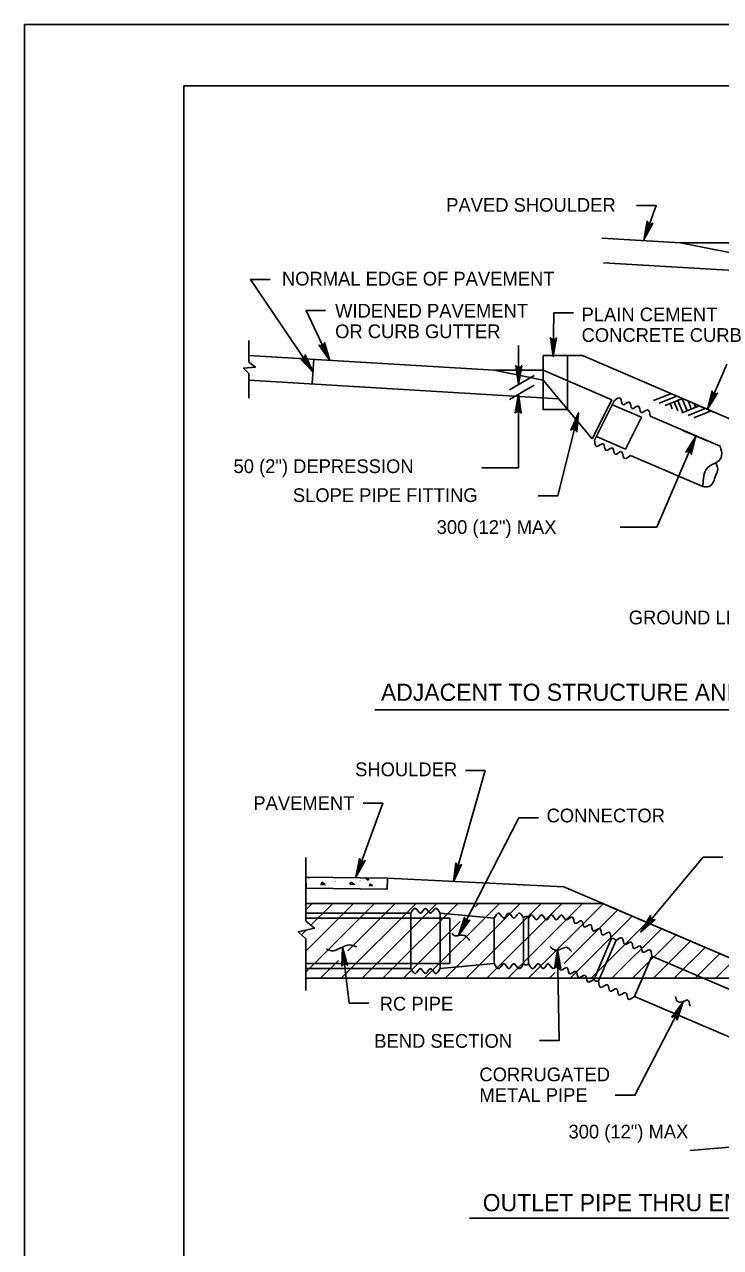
# Model space of a CAD drawing. Extents: x 637898 to 638802, y 298167 to 298761.
# Drawn here: x 637898 to 638068.2, y 298461.7 to 298760.9 of the extents above; entities that cross this region are included whole.
import ezdxf

# ---------------------------------------------------------------- set-up
doc = ezdxf.new("R2010")
doc.units = 0
for name, color, linetype in [('1', 7, 'Continuous'), ('2', 7, 'Continuous'), ('3', 7, 'Continuous'), ('PLT-BNDY', 7, 'Continuous')]:
    doc.layers.add(name, color=color, linetype=linetype)

msp = doc.modelspace()

# ---------------------------------------------------------------- linework, layer by layer
at = {"layer": '1'}
msp.add_lwpolyline([(638722.97, 298181.88), (638722.97, 298745.88), (637936.97, 298745.88), (637936.97, 298181.88), (638722.97, 298181.88), (638722.97, 298208.24), (638522.97, 298208.24), (638522.97, 298272.92), (638722.97, 298272.92), (638722.97, 298301.88), (638522.97, 298301.88), (638522.97, 298181.88), (638601.78, 298181.88), (638601.78, 298208.24), (638601.78, 298181.88), (638678.78, 298181.88), (638678.78, 298208.24), (638678.78, 298195.92), (638722.97, 298195.92)], dxfattribs=at)
at = {"layer": '2'}
for p, q in [((638039.16, 298708.64), (638058.42, 298707.48)), ((638058.42, 298707.48), (638070.42, 298705.08)), ((638039.61, 298702.6), (638074.22, 298700.52)), ((637952.82, 298683.56), (637952.82, 298678.27)), ((637952.82, 298679.88), (638012.82, 298676.28)), ((638018.81, 298672.82), (638018.81, 298682.31)), ((638024.82, 298676.28), (638024.82, 298679.88)), ((638024.82, 298679.88), (638034.42, 298679.88)), ((637968.73, 298679.04), (637968.37, 298673.05)), ((638069.71, 298677.75), (638065, 298666.74)), ((637952.82, 298675.54), (637952.82, 298669.44)), ((637952.82, 298673.87), (638028.62, 298669.32)), ((638012.82, 298676.28), (638024.82, 298673.88)), ((638022.66, 298675.04), (638016.58, 298671.53)), ((638041.62, 298669.08), (638024.82, 298676.28)), ((638024.82, 298673.88), (638036.82, 298659.48)), ((638022.66, 298672.64), (638016.58, 298669.13)), ((638036.82, 298659.48), (638041.62, 298669.08)), ((638037.35, 298659.21), (638042.16, 298668.81)), ((638042.16, 298668.81), (638042.16, 298668.81)), ((638051.85, 298668.88), (638056.07, 298670.56)), ((638053.23, 298668.28), (638057.48, 298669.98)), ((638054.66, 298667.67), (638058.91, 298669.37)), ((638055.87, 298668.15), (638056.38, 298666.88)), ((638056.89, 298668.56), (638057.78, 298666.34)), ((638057.8, 298668.92), (638058.96, 298666)), ((638058.84, 298669.4), (638060.04, 298666.4)), ((638060.27, 298668.78), (638061.05, 298666.83)), ((638061.72, 298668.16), (638062.09, 298667.23)), ((638061.79, 298668.12), (638067.76, 298665.56)), ((638044.36, 298667.87), (638044.36, 298667.87)), ((638044.36, 298667.87), (638044.36, 298667.87)), ((638046.57, 298666.92), (638046.57, 298666.92)), ((638046.57, 298666.92), (638046.57, 298666.92)), ((638048.77, 298665.98), (638048.77, 298665.98)), ((638050.98, 298665.03), (638050.98, 298665.03)), ((638068.11, 298657.69), (638050.98, 298665.03)), ((638058.78, 298665.91), (638063.04, 298667.61)), ((638060.29, 298665.26), (638064.48, 298666.94)), ((638061.71, 298664.65), (638065.91, 298666.33)), ((638053.19, 298664.09), (638053.19, 298664.09)), ((638055.39, 298663.14), (638055.39, 298663.14)), ((638057.6, 298662.2), (638057.6, 298662.2)), ((638037.35, 298659.21), (638037.35, 298659.21)), ((638058.99, 298661.59), (638064.95, 298659.03)), ((638059.8, 298661.25), (638059.8, 298661.25)), ((638062.01, 298660.31), (638062.01, 298660.31)), ((638064.21, 298659.36), (638064.21, 298659.36)), ((638043.97, 298656.38), (638043.97, 298656.38)), ((638066.42, 298658.42), (638066.42, 298658.42)), ((638046.18, 298655.43), (638046.18, 298655.43)), ((638063.89, 298647.84), (638046.18, 298655.43)), ((638048.39, 298654.49), (638048.39, 298654.49)), ((638050.59, 298653.54), (638050.59, 298653.54)), ((638052.8, 298652.6), (638052.8, 298652.6)), ((638055, 298651.65), (638055, 298651.65)), ((638057.21, 298650.71), (638057.21, 298650.71)), ((638059.42, 298649.76), (638059.42, 298649.76)), ((638061.62, 298648.82), (638061.62, 298648.82)), ((638063.83, 298647.87), (638063.83, 298647.87)), ((637966.76, 298557.09), (637966.76, 298541.57)), ((637986.74, 298552.08), (638029.92, 298549.91)), ((638080.36, 298528.3), (638029.92, 298549.91)), ((638039.35, 298545.87), (637966.76, 298545.87)), ((637992.44, 298543.47), (637966.76, 298543.47)), ((638002.04, 298542.27), (637966.76, 298542.27)), ((637984.04, 298542.27), (637984.04, 298542.27)), ((637986.44, 298542.27), (637986.44, 298542.27)), ((637986.44, 298542.27), (637986.44, 298542.27)), ((637988.84, 298542.27), (637988.84, 298542.27)), ((637991.24, 298542.27), (637991.24, 298542.27)), ((637992.44, 298543.47), (637992.44, 298529.95)), ((637993.64, 298542.27), (637993.64, 298542.27)), ((637996.04, 298542.27), (637996.04, 298542.27)), ((637998.44, 298542.27), (637998.44, 298542.27)), ((637999.64, 298543.47), (637999.64, 298529.95)), ((638012.84, 298542.27), (637999.64, 298543.47)), ((638000.84, 298542.27), (638000.84, 298542.27)), ((638002.04, 298542.27), (638002.04, 298531.15)), ((638003.24, 298542.27), (638003.24, 298542.27)), ((638005.64, 298542.27), (638005.64, 298542.27)), ((638008.04, 298542.27), (638008.04, 298542.27)), ((638010.44, 298542.27), (638010.44, 298542.27)), ((638012.84, 298542.27), (638012.84, 298542.27)), ((638012.84, 298531.15), (638012.84, 298542.27)), ((638015.24, 298542.27), (638015.24, 298542.27)), ((638017.64, 298542.27), (638017.64, 298542.27)), ((638020.04, 298531.15), (638020.04, 298542.27)), ((638020.04, 298542.27), (638020.04, 298542.27)), ((638021.24, 298531.15), (638021.24, 298542.27)), ((638020.84, 298541.87), (638020.84, 298541.87)), ((638023.24, 298541.87), (638023.24, 298541.87)), ((638025.64, 298541.87), (638025.64, 298541.87)), ((638028.04, 298541.87), (638028.04, 298541.87)), ((638030.44, 298541.87), (638030.44, 298541.87)), ((638032.66, 298541), (638032.66, 298541)), ((638034.87, 298540.06), (638034.87, 298540.06)), ((637966.76, 298537.23), (637966.76, 298524.61)), ((638037.08, 298539.11), (638037.08, 298539.11)), ((638041.49, 298537.22), (638037.27, 298527.37)), ((638042.59, 298536.75), (638038.37, 298526.9)), ((638039.28, 298538.17), (638039.28, 298538.17)), ((638041.49, 298537.22), (638041.49, 298537.22)), ((638002.04, 298531.15), (637966.76, 298531.15)), ((637984.04, 298531.15), (637984.04, 298531.15)), ((637986.44, 298531.15), (637986.44, 298531.15)), ((637986.44, 298531.15), (637986.44, 298531.15)), ((637988.84, 298531.15), (637988.84, 298531.15)), ((637991.24, 298531.15), (637991.24, 298531.15)), ((637993.64, 298531.15), (637993.64, 298531.15)), ((637996.04, 298531.15), (637996.04, 298531.15)), ((637998.44, 298531.15), (637998.44, 298531.15)), ((638012.84, 298531.15), (637999.64, 298529.95)), ((638000.84, 298531.15), (638000.84, 298531.15)), ((638003.24, 298531.15), (638003.24, 298531.15)), ((638005.64, 298531.15), (638005.64, 298531.15)), ((638008.04, 298531.15), (638008.04, 298531.15)), ((638010.44, 298531.15), (638010.44, 298531.15)), ((638012.84, 298531.15), (638012.84, 298531.15)), ((638015.24, 298531.15), (638015.24, 298531.15)), ((638017.64, 298531.15), (638017.64, 298531.15)), ((638020.04, 298531.15), (638020.04, 298531.15)), ((638021.24, 298531.15), (638021.24, 298531.15)), ((638023.64, 298531.15), (638023.64, 298531.15)), ((638026.04, 298531.15), (638026.04, 298531.15)), ((638028.44, 298531.15), (638028.44, 298531.15)), ((638051.41, 298532.97), (638047.19, 298523.12)), ((638051.41, 298532.97), (638077.37, 298521.84)), ((637992.44, 298529.95), (637966.76, 298529.95)), ((638081.26, 298527.55), (637966.76, 298527.55)), ((638030.65, 298530.21), (638030.65, 298530.21)), ((638032.86, 298529.26), (638032.86, 298529.26)), ((638035.06, 298528.32), (638035.06, 298528.32)), ((638037.27, 298527.37), (638037.27, 298527.37)), ((638047.19, 298523.12), (638073.15, 298512)), ((638006.78, 298468.88), (638148.19, 298468.88))]:
    msp.add_line(p, q, dxfattribs=at)
for points in [[(638047.62, 298716.61), (638052.43, 298716.61), (638049.47, 298708.19)], [(638051.43, 298712.12), (638051.08, 298712.07), (638049.47, 298708.19), (638051.43, 298712.12), (638051.69, 298712.27), (638049.47, 298708.19), (638050.67, 298712.22), (638050.42, 298712.46), (638049.47, 298708.19), (638050.3, 298712.76), (638050.42, 298712.46)], [(638058.42, 298707.48), (638075.21, 298707.48)], [(637958.05, 298698.47), (637953.25, 298698.47), (637968.54, 298675.82)], [(637971.63, 298690.94), (637966.83, 298690.94), (637972.66, 298678.61)], [(638032.22, 298690.32), (638027.42, 298690.32), (638027.29, 298679.64)], [(637971.29, 298682.79), (637971.07, 298682.51), (637972.66, 298678.61), (637971.29, 298682.79), (637971.36, 298683.07), (637972.66, 298678.61), (637970.68, 298682.32), (637970.33, 298682.32), (637972.66, 298678.61), (637970.04, 298682.44), (637970.33, 298682.32)], [(638027.89, 298683.99), (638027.57, 298683.83), (638027.29, 298679.64), (638027.89, 298683.99), (638028.08, 298684.21), (638027.29, 298679.64), (638027.14, 298683.84), (638026.83, 298683.99), (638027.29, 298679.64), (638026.62, 298684.23), (638026.83, 298683.99)], [(637966.56, 298679.74), (637966.38, 298679.42), (637968.54, 298675.82), (637966.56, 298679.74), (637966.59, 298680.03), (637968.54, 298675.82), (637966.02, 298679.18), (637965.68, 298679.13), (637968.54, 298675.82), (637965.37, 298679.21), (637965.68, 298679.13)], [(638012.82, 298676.28), (638024.82, 298676.28), (638024.82, 298666.68), (638030.82, 298666.68), (638030.82, 298679.88)], [(638034.41, 298679.87), (638071.24, 298664.08)], [(637952.82, 298678.27), (637954.45, 298677.05), (637951.55, 298676.81), (637952.82, 298675.54)], [(638019.41, 298677.17), (638019.09, 298677.01), (638018.81, 298672.82), (638019.41, 298677.17), (638019.6, 298677.39), (638018.81, 298672.82), (638018.65, 298677.01), (638018.34, 298677.17), (638018.81, 298672.82), (638018.13, 298677.41), (638018.34, 298677.17)], [(638067.22, 298670.53), (638066.87, 298670.51), (638065, 298666.74), (638067.22, 298670.53), (638067.48, 298670.66), (638065, 298666.74), (638066.46, 298670.68), (638066.24, 298670.94), (638065, 298666.74), (638066.14, 298671.24), (638066.24, 298670.94)], [(638018.2, 298666.06), (638018.52, 298666.22), (638018.81, 298670.42), (638018.2, 298666.06), (638018.01, 298665.84), (638018.81, 298670.42), (638018.96, 298666.22), (638019.27, 298666.06), (638018.81, 298670.42), (638019.48, 298665.82), (638019.27, 298666.06)], [(638018.81, 298670.42), (638018.81, 298652.42)], [(638023.59, 298645.54), (638028.4, 298645.54), (638033.45, 298665.88)], [(638031.87, 298661.78), (638032.21, 298661.86), (638033.45, 298665.88), (638031.87, 298661.78), (638031.63, 298661.61), (638033.45, 298665.88), (638032.64, 298661.76), (638032.91, 298661.54), (638033.45, 298665.88), (638033.05, 298661.26), (638032.91, 298661.54)], [(638037.84, 298660.09), (638044.98, 298657.03), (638048.87, 298664.8), (638041.72, 298667.87)], [(638062.2, 298660.21), (638052.65, 298637.94)], [(638059.97, 298656.42), (638060.33, 298656.45), (638062.2, 298660.21), (638059.97, 298656.42), (638059.71, 298656.29), (638062.2, 298660.21), (638060.73, 298656.28), (638060.96, 298656.01), (638062.2, 298660.21), (638061.06, 298655.71), (638060.96, 298656.01)], [(638009.81, 298652.42), (638018.81, 298652.42)], [(638052.65, 298637.94), (638043.65, 298637.94)], [(638005.84, 298578.42), (638010.64, 298578.42), (638002.94, 298551.18)], [(637980.83, 298570.38), (637985.63, 298570.38), (637979.05, 298552.3)], [(638023.7, 298566.81), (638018.9, 298566.81), (638004.11, 298538.03)], [(638068.8, 298557.21), (638064, 298557.21), (638048.7, 298538.9)], [(637981.05, 298556.2), (637980.7, 298556.16), (637979.05, 298552.3), (637981.05, 298556.2), (637981.31, 298556.35), (637979.05, 298552.3), (637980.29, 298556.31), (637980.05, 298556.56), (637979.05, 298552.3), (637979.93, 298556.85), (637980.05, 298556.56)], [(638004.65, 298555.22), (638004.3, 298555.15), (638002.94, 298551.18), (638004.65, 298555.22), (638004.89, 298555.39), (638002.94, 298551.18), (638003.88, 298555.27), (638003.62, 298555.5), (638002.94, 298551.18), (638003.48, 298555.79), (638003.62, 298555.5)], [(637966.84, 298549.64), (637986.71, 298549.39), (637986.74, 298552.08), (637966.77, 298552.32)], [(637967.52, 298552.05), (637967.24, 298552.32)], [(637967.52, 298552.31), (637967.52, 298552.05)], [(637981.38, 298552.14), (637982.01, 298551.58)], [(637982.01, 298551.58), (637982.22, 298552.13)], [(637983.98, 298552.05), (637983.91, 298552.11)], [(637983.98, 298552.11), (637983.98, 298552.05)], [(637966.76, 298529.07), (637983.57, 298545.87)], [(637966.76, 298534.16), (637978.48, 298545.87)], [(637966.76, 298544.34), (637968.3, 298545.87)], [(637968.03, 298540.52), (637973.39, 298545.87)], [(637975.43, 298527.55), (637993.75, 298545.87)], [(637977.05, 298534.26), (637988.66, 298545.87)], [(637980.53, 298527.55), (637998.84, 298545.87)], [(637985.62, 298527.55), (638003.93, 298545.87)], [(637995.8, 298527.55), (638014.12, 298545.87)], [(638000.89, 298527.55), (638019.21, 298545.87)], [(638005.98, 298527.55), (638024.3, 298545.87)], [(638008.09, 298544.94), (638009.02, 298545.87)], [(638011.07, 298527.55), (638029.39, 298545.87)], [(638016.16, 298527.55), (638034.48, 298545.87)], [(638021.26, 298527.55), (638039.5, 298545.8)], [(638006.59, 298541.66), (638006.24, 298541.66), (638004.11, 298538.03), (638006.59, 298541.66), (638006.86, 298541.77), (638004.11, 298538.03), (638005.84, 298541.85), (638005.64, 298542.13), (638004.11, 298538.03), (638005.56, 298542.44), (638005.64, 298542.13)], [(638029.96, 298531.16), (638043.07, 298544.28)], [(638031.44, 298527.55), (638046.63, 298542.75)], [(638051.92, 298541.89), (638051.57, 298541.97), (638048.7, 298538.9), (638051.92, 298541.89), (638052.21, 298541.94), (638048.7, 298538.9), (638051.23, 298542.25), (638051.09, 298542.57), (638048.7, 298538.9), (638051.08, 298542.88), (638051.09, 298542.57)], [(637966.76, 298541.57), (637968.89, 298539.81), (637964.95, 298538.94), (637966.76, 298537.23)], [(637965.73, 298538.21), (637966.88, 298539.36)], [(637990.71, 298527.55), (638004.57, 298541.42)], [(638036.53, 298527.55), (638050.2, 298541.22)], [(638041.62, 298527.55), (638053.76, 298539.69)], [(638046.71, 298527.55), (638057.32, 298538.17)], [(638051.8, 298527.55), (638060.89, 298536.64)], [(637975.72, 298530.8), (637976.01, 298531), (637975.75, 298535.2), (637975.72, 298530.8), (637975.56, 298530.56), (637975.75, 298535.2), (637976.45, 298531.06), (637976.78, 298530.94), (637975.75, 298535.2), (637977.01, 298530.73), (637976.78, 298530.94)], [(637982.17, 298521.49), (637977.37, 298521.49), (637975.75, 298535.2)], [(638023.92, 298512.33), (638028.72, 298512.33), (638028.3, 298534.57)], [(638027.83, 298530.2), (638028.14, 298530.37), (638028.3, 298534.57), (638027.83, 298530.2), (638027.64, 298529.97), (638028.3, 298534.57), (638028.58, 298530.38), (638028.9, 298530.23), (638028.3, 298534.57), (638029.11, 298530), (638028.9, 298530.23)], [(638056.89, 298527.55), (638064.45, 298535.11)], [(638061.98, 298527.55), (638068.02, 298533.59)], [(637970.34, 298527.55), (637974.74, 298531.95)], [(638067.08, 298527.55), (638071.58, 298532.06)], [(638026.35, 298527.55), (638027.74, 298528.95)], [(638042.45, 298498.94), (638047.25, 298498.94), (638059.06, 298521.77)], [(638056.57, 298518.15), (638056.92, 298518.15), (638059.06, 298521.77), (638056.57, 298518.15), (638056.3, 298518.04), (638059.06, 298521.77), (638057.31, 298517.95), (638057.52, 298517.67), (638059.06, 298521.77), (638057.6, 298517.36), (638057.52, 298517.67)], [(638060.82, 298485.41), (638070.42, 298486.24)]]:
    msp.add_lwpolyline(points, dxfattribs=at)
for points in [[(637966.77, 298552.32), (637986.74, 298552.08), (637986.71, 298549.39), (637966.84, 298549.64)], [(637970.43, 298550.43), (637970.8, 298551.04), (637971.44, 298550.48)], [(637977.52, 298550.59), (637977.8, 298551.04), (637978.7, 298550.54)], [(637982.33, 298550.14), (637982.56, 298550.59), (637983.09, 298550.26)], [(637968.89, 298539.81), (637966.76, 298541.57), (637966.76, 298545.87), (638039.35, 298545.87), (638080.36, 298528.3), (638081.26, 298527.55), (637966.76, 298527.55), (637966.76, 298537.23), (637964.95, 298538.94)]]:
    msp.add_lwpolyline(points, close=True, dxfattribs=at)
for centre, radius, start, end in [((638020.64, 298542.07), 0.633, 18.7071, 161.2929), ((638020.64, 298531.51), 0.698, 210.7717, 329.2283)]:
    msp.add_arc(centre, radius, start, end, dxfattribs=at)
for points in [[(638050.98, 298665.03), (638050.35, 298666.61), (638048.77, 298665.98), (638048.14, 298667.55), (638046.57, 298666.92), (638045.94, 298668.5), (638044.36, 298667.87), (638043.73, 298669.45), (638042.16, 298668.81)], [(638037.35, 298659.21), (638037.98, 298657.64), (638039.56, 298658.27), (638040.19, 298656.69), (638041.77, 298657.32), (638042.4, 298655.75), (638043.97, 298656.38), (638044.6, 298654.8), (638046.18, 298655.43)], [(638068.11, 298657.69), (638068.46, 298655.35), (638067.53, 298653.94), (638065.49, 298652.85), (638064.24, 298650.97), (638063.93, 298648.63), (638063.89, 298647.84)], [(638063.89, 298647.84), (638065.34, 298647.85), (638066.43, 298648.94), (638067.06, 298650.66), (638067.53, 298652.07), (638067.06, 298653.63)], [(637999.64, 298543.47), (637998.44, 298544.67), (637997.24, 298543.47), (637996.04, 298544.67), (637994.84, 298543.47), (637993.64, 298544.67), (637992.44, 298543.47)], [(638020.04, 298542.27), (638018.84, 298543.47), (638017.64, 298542.27), (638016.44, 298543.47), (638015.24, 298542.27), (638014.04, 298543.47), (638012.84, 298542.27)], [(638041.49, 298537.22), (638040.86, 298538.8), (638039.28, 298538.17), (638038.65, 298539.74), (638037.08, 298539.11), (638036.45, 298540.69), (638034.87, 298540.06), (638034.24, 298541.63), (638032.66, 298541), (638031.99, 298542.55), (638030.44, 298541.87), (638029.24, 298543.07), (638028.04, 298541.87), (638026.84, 298543.07), (638025.64, 298541.87), (638024.44, 298543.07), (638023.24, 298541.87), (638022.04, 298543.07), (638021.26, 298542.29)], [(638002.57, 298538.61), (638003.05, 298538.03), (638004.3, 298538.03), (638005.94, 298537.84), (638006.81, 298536.78)], [(638041.49, 298537.22), (638042.17, 298537.28), (638042.59, 298536.75)], [(638051.41, 298532.97), (638050.78, 298534.54), (638049.21, 298533.91), (638048.58, 298535.49), (638047, 298534.86), (638046.37, 298536.43), (638044.8, 298535.8), (638044.17, 298537.38), (638042.59, 298536.75)], [(637971.83, 298534.75), (637973.57, 298534.27), (637974.72, 298534.75), (637975.88, 298535.24), (637977.42, 298535.72), (637979.25, 298535.24)], [(638026.56, 298535.24), (638027.71, 298534.47), (638029.35, 298534.75), (638030.51, 298535.14), (638031.76, 298534.08)], [(638020.04, 298531.15), (638018.84, 298529.95), (638017.64, 298531.15), (638016.44, 298529.95), (638015.24, 298531.15), (638014.04, 298529.95), (638012.84, 298531.15)], [(638037.27, 298527.37), (638035.69, 298526.74), (638035.06, 298528.32), (638033.49, 298527.69), (638032.86, 298529.26), (638031.28, 298528.63), (638030.65, 298530.21), (638029.07, 298529.58), (638028.44, 298531.15), (638027.24, 298529.95), (638026.04, 298531.15), (638024.84, 298529.95), (638023.64, 298531.15), (638022.44, 298529.95), (638021.24, 298531.15)], [(637999.64, 298529.95), (637998.44, 298528.75), (637997.24, 298529.95), (637996.04, 298528.75), (637994.84, 298529.95), (637993.64, 298528.75), (637992.44, 298529.95)], [(638038.37, 298526.9), (638037.69, 298526.84), (638037.27, 298527.37)], [(638038.37, 298526.9), (638039, 298525.32), (638040.58, 298525.95), (638041.21, 298524.38), (638042.78, 298525.01), (638043.41, 298523.43), (638044.99, 298524.06), (638045.62, 298522.49), (638047.19, 298523.12)], [(638057.22, 298523.14), (638057.64, 298522), (638058.88, 298521.8), (638060.12, 298522.21), (638060.74, 298520.76)]]:
    msp.add_spline(points, degree=3, dxfattribs=at)
at = {"layer": '3'}
msp.add_line((637983.65, 298593.22), (638165.1, 298593.22), dxfattribs=at)
at = {"layer": 'PLT-BNDY'}
msp.add_lwpolyline([(637897.97, 298760.88), (638738.97, 298760.88), (638738.97, 298166.88), (637897.97, 298166.88)], close=True, dxfattribs=at)

# ---------------------------------------------------------------- texts
at = {"layer": '2'}
for s, height, p in [('.', 1.12, (637973.9, 298551.11)), ('.', 1.12, (637979.84, 298551.31)), ('OUTLET PIPE THRU EMBANKMENT SLOPE', 4.2, (638010.05, 298470.58))]:
    msp.add_text(s, height=height, dxfattribs=at).set_placement(p)
at = {"layer": '3'}
for s, height, p in [('PAVED SHOULDER', 3.36, (638001.12, 298715.06)), ('NORMAL EDGE OF PAVEMENT', 3.36, (637960.94, 298697.02)), ('WIDENED PAVEMENT', 3.36, (637973.95, 298689.18)), ('PLAIN CEMENT', 3.36, (638034.22, 298688.27)), ('OR CURB GUTTER', 3.36, (637973.95, 298684.14)), ('CONCRETE CURB', 3.36, (638034.22, 298683.23)), ('50 (2") DEPRESSION', 3.36, (637949.1, 298651.14)), ('SLOPE PIPE FITTING', 3.36, (637963.61, 298644.06)), ('300 (12") MAX', 3.36, (637998.78, 298636.26)), ('GROUND LINE', 3.36, (638045.75, 298614.14)), ('ADJACENT TO STRUCTURE AND/OR PAVED SHOULDER', 4.2, (637985.15, 298595.43)), ('SHOULDER', 3.36, (637978.84, 298576.99)), ('PAVEMENT', 3.36, (637953.95, 298568.74)), ('CONNECTOR', 3.36, (638025.66, 298565.7)), ('RC PIPE', 3.36, (637984.85, 298519.67)), ('BEND SECTION', 3.36, (637983.52, 298510.55)), ('CORRUGATED', 3.36, (638009.23, 298502.36)), ('METAL PIPE', 3.36, (638009.23, 298497.32)), ('300 (12") MAX', 3.36, (638031.02, 298488.38))]:
    msp.add_text(s, height=height, dxfattribs=at).set_placement(p)

doc.saveas('drawing.dxf')
